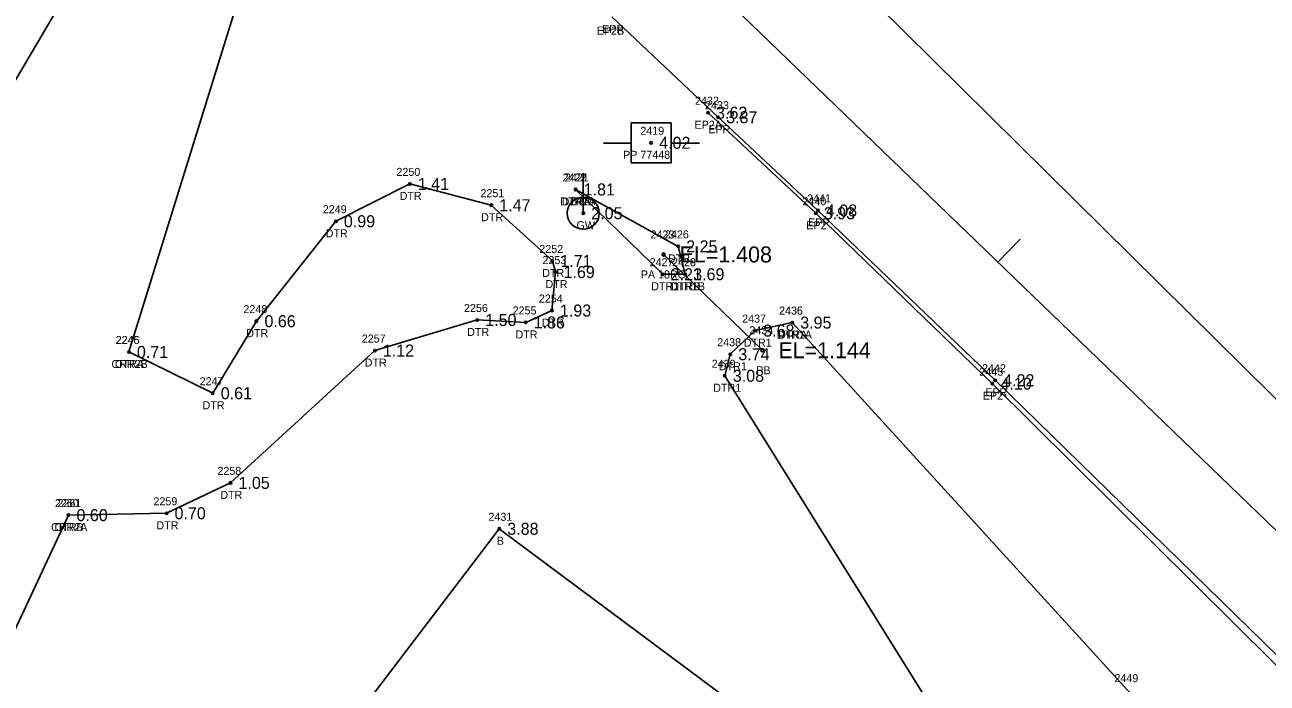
# Model space of a CAD drawing. Extents: x 2608598 to 2610682, y 641451 to 643526.
# Drawn here: x 2609905.8 to 2610061, y 642151 to 642233.2 of the extents above; entities that cross this region are included whole.
import ezdxf

# ---------------------------------------------------------------- set-up
doc = ezdxf.new("R2010")
doc.units = 0
for name, color, linetype in [('RD_EX_Bldg', 7, 'Continuous'), ('RD_EX_Bldg_txCode', 7, 'Continuous'), ('RD_EX_DR_Pipe', 7, 'Continuous'), ('RD_EX_DR_Pipe_txCode', 7, 'Continuous'), ('RD_EX_H2O', 7, 'Continuous'), ('RD_EX_H2O_txCode', 7, 'Continuous'), ('RD_EX_Road', 7, 'Continuous'), ('RD_EX_Road_txCode', 7, 'Continuous'), ('RD_EX_TX_Bldg_ELEV', 7, 'Continuous'), ('RD_EX_TX_H2O_ELEV', 7, 'Continuous'), ('RD_EX_TX_Road_ELEV', 7, 'Continuous'), ('RD_EX_TX_UT_ELEV', 7, 'Continuous'), ('RD_EX_UT', 7, 'Continuous'), ('RD_EX_UT_txCode', 7, 'Continuous'), ('RD_HC_Cl', 7, 'Continuous'), ('RD_HC_Data_Tic', 7, 'Continuous'), ('RD_HC_Survey_ELEV', 7, 'Continuous'), ('RD_SMD_Locator', 7, 'Continuous'), ('RD_TX_Pipe_ElevEX', 7, 'Continuous')]:
    doc.layers.add(name, color=color, linetype=linetype)

msp = doc.modelspace()

# ---------------------------------------------------------------- linework, layer by layer
at = {"layer": 'RD_EX_Bldg'}
msp.add_lwpolyline([(2609946.85, 642146.35), (2609965.06, 642170.24), (2610017.88, 642130.88), (2610000.02, 642106.61), (2609946.85, 642146.35)], dxfattribs=at)
at = {"layer": 'RD_EX_DR_Pipe'}
msp.add_line((2609985.59, 642204.51), (2609997.93, 642192.55), dxfattribs=at)
at = {"layer": 'RD_EX_H2O'}
for points in [[(2609550.15, 642638.19), (2609560.64, 642608.55), (2609596.58, 642544.67), (2609665.26, 642493.63), (2609726.89, 642435.57), (2609728.97, 642442.01), (2609745.88, 642433.78), (2609753.45, 642414.77), (2609764.24, 642411.87), (2609765.65, 642391.82), (2609764.35, 642384.35), (2609816.5, 642340.65), (2609898.67, 642278.63), (2609932.36, 642236.09), (2609918.8, 642192.33)], [(2609918.8, 642192.33), (2609929.27, 642187.18), (2609934.73, 642196.18), (2609944.65, 642208.66), (2609953.89, 642213.33), (2609964.06, 642210.67), (2609971.69, 642203.7), (2609972.09, 642202.31), (2609971.64, 642197.51), (2609968.36, 642196.02), (2609962.31, 642196.33), (2609949.52, 642192.51), (2609931.49, 642175.98), (2609923.5, 642172.18), (2609911.25, 642171.95)], [(2609974.6, 642212.63), (2609985.47, 642202.04), (2609988.28, 642202.04)], [(2609974.6, 642212.63), (2609987.41, 642205.52), (2609988.28, 642202.04)], [(2610001.65, 642196), (2609997.03, 642195), (2609993.92, 642192.05), (2609993.23, 642189.36), (2610025.09, 642138.24), (2610033.21, 642127.17), (2610029.91, 642117.96), (2610026.91, 642107.17), (2610030.12, 642088.07)], [(2610001.65, 642196), (2610043.53, 642150.08), (2610051.56, 642141.98), (2610057.33, 642129.72), (2610057.88, 642123.71), (2610050.62, 642108.28), (2610045.52, 642100), (2610039.29, 642092.45), (2610036.01, 642087.34), (2610033.47, 642085.84), (2610030.12, 642088.07)], [(2609911.25, 642171.95), (2609899.14, 642146.07), (2609837.93, 642059.5)]]:
    msp.add_lwpolyline(points, dxfattribs=at)
at = {"layer": 'RD_EX_Road'}
for points in [[(2609576.61, 642656.06), (2609590.88, 642642.24), (2609605.19, 642628.78), (2609627.58, 642607.09), (2609646.03, 642589.11), (2609702.18, 642534.04), (2609780.35, 642458.95), (2609858.79, 642382.83), (2609938.32, 642306.42), (2610008.62, 642239.32), (2610086.3, 642162.54), (2610164.18, 642089.49), (2610189.2, 642065.46), (2610214.78, 642040.19), (2610225.86, 642030.16), (2610226.32, 642028.39), (2610235.43, 642019.75), (2610260.23, 641995.63), (2610272.39, 641983.25)], [(2609979.13, 642234.19), (2609992.4, 642221.66), (2610004.86, 642210.01), (2610027, 642188.8), (2610067.64, 642149.14), (2610070.8, 642146.19), (2610073.96, 642143.05), (2610116.51, 642103.01), (2610119.68, 642100.06), (2610135.09, 642085.92), (2610148.33, 642073.03), (2610165.14, 642055.61), (2610179.59, 642041.57), (2610196.49, 642024.71), (2610209.86, 642011.42), (2610228.39, 641994.06), (2610252.93, 641970.08), (2610256.35, 641966.74)], [(2609991.14, 642222.22), (2610004.6, 642209.66), (2610026.66, 642188.37), (2610066.82, 642148.56), (2610069.65, 642145.36), (2610071.05, 642141.53), (2610071.68, 642138.94), (2610071.34, 642133.72), (2610072.62, 642129.27)]]:
    msp.add_lwpolyline(points, dxfattribs=at)
at = {"layer": 'RD_EX_UT'}
for p, q in [((2609986.52, 642220.97), (2609981.52, 642220.97)), ((2609981.52, 642220.97), (2609981.52, 642215.97)), ((2609986.52, 642215.97), (2609986.52, 642220.97)), ((2609978.09, 642218.41), (2609981.56, 642218.41)), ((2609986.45, 642218.41), (2609990.09, 642218.41)), ((2609981.52, 642215.97), (2609986.52, 642215.97)), ((2609975.55, 642209.67), (2609975.55, 642214.67))]:
    msp.add_line(p, q, dxfattribs=at)
msp.add_circle((2609975.55, 642209.67), 2, dxfattribs=at)
at = {"layer": 'RD_HC_Cl'}
for p, q in [((2608814.81, 643373.73), (2610092.39, 642140.79)), ((2609912.02, 642238.9), (2609870.22, 642167.84))]:
    msp.add_line(p, q, dxfattribs=at)
at = {"layer": 'RD_HC_Data_Tic'}
msp.add_line((2610027.34, 642203.56), (2610030.12, 642206.44), dxfattribs=at)
at = {"layer": 'RD_SMD_Locator'}
for centre, radius in [((2609991.14, 642222.22), 0.15), ((2609992.4, 642221.66), 0.15), ((2609984.03, 642218.46), 0.15), ((2609953.89, 642213.33), 0.15), ((2609974.6, 642212.63), 0.15), ((2609974.6, 642212.63), 0.15), ((2609964.06, 642210.67), 0.15), ((2609975.55, 642209.67), 0.15), ((2610004.6, 642209.66), 0.15), ((2610004.86, 642210.01), 0.15), ((2609944.65, 642208.66), 0.15), ((2609985.59, 642204.51), 0.2), ((2609987.41, 642205.52), 0.15), ((2609971.69, 642203.7), 0.15), ((2609972.09, 642202.31), 0.15), ((2609985.47, 642202.04), 0.15), ((2609988.28, 642202.04), 0.15), ((2609988.28, 642202.04), 0.15), ((2609971.64, 642197.51), 0.15), ((2609934.73, 642196.18), 0.15), ((2609962.31, 642196.33), 0.15), ((2609968.36, 642196.02), 0.15), ((2610001.65, 642196), 0.15), ((2610001.65, 642196), 0.15), ((2609997.03, 642195), 0.15), ((2609918.8, 642192.33), 0.15), ((2609918.8, 642192.33), 0.15), ((2609949.52, 642192.51), 0.15), ((2609993.92, 642192.05), 0.15), ((2609997.93, 642192.55), 0.2), ((2609993.23, 642189.36), 0.15), ((2610026.66, 642188.37), 0.15), ((2610027, 642188.8), 0.15), ((2609929.27, 642187.18), 0.15), ((2609931.49, 642175.98), 0.15), ((2609911.25, 642171.95), 0.15), ((2609911.25, 642171.95), 0.15), ((2609923.5, 642172.18), 0.15), ((2609965.06, 642170.24), 0.15)]:
    msp.add_circle(centre, radius, dxfattribs=at)

# ---------------------------------------------------------------- texts
at = {"layer": 'RD_EX_Bldg_txCode'}
for s, p in [('2431', (2609963.71, 642171.24)), ('B', (2609964.75, 642168.24))]:
    msp.add_text(s, height=1, dxfattribs=at).set_placement(p)
at = {"layer": 'RD_EX_DR_Pipe_txCode'}
for s, p in [('2423', (2609983.96, 642206.51)), ('PA 18RC', (2609982.74, 642201.51)), ('2434', (2609996.3, 642194.55)), ('PB', (2609997.16, 642189.55))]:
    msp.add_text(s, height=1, dxfattribs=at).set_placement(p)
at = {"layer": 'RD_EX_H2O_txCode'}
for s, p in [('2250', (2609952.22, 642214.33)), ('2422', (2609972.97, 642213.63)), ('2421', (2609973.26, 642213.63)), ('2251', (2609962.71, 642211.67)), ('DTR', (2609952.62, 642211.33)), ('DTR1A', (2609972.68, 642210.63)), ('DTRA', (2609972.85, 642210.63)), ('2249', (2609943.02, 642209.66)), ('DTR', (2609962.79, 642208.67)), ('DTR', (2609943.38, 642206.66)), ('2426', (2609985.76, 642206.52)), ('2252', (2609970.06, 642204.7)), ('2253', (2609970.46, 642203.31)), ('2427', (2609983.84, 642203.04)), ('DTR', (2609986.14, 642203.52)), ('2428', (2609986.65, 642203.04)), ('2429', (2609986.65, 642203.04)), ('DTR', (2609970.43, 642201.7)), ('DTR', (2609970.83, 642200.31)), ('DTR1', (2609984.04, 642200.04)), ('DTR1B', (2609986.38, 642200.04)), ('DTRB', (2609986.54, 642200.04)), ('2254', (2609970.01, 642198.51)), ('2248', (2609933.1, 642197.18)), ('2256', (2609960.66, 642197.33)), ('2255', (2609966.73, 642197.02)), ('2437', (2609995.4, 642196)), ('2436', (2610000, 642197)), ('2435', (2610000.02, 642197)), ('DTR', (2609961.05, 642194.33)), ('DTR', (2609970.37, 642195.51)), ('2246', (2609917.14, 642193.33)), ('2245', (2609917.17, 642193.33)), ('DTR', (2609933.46, 642194.18)), ('2257', (2609947.89, 642193.51)), ('DTR', (2609967.09, 642194.02)), ('2438', (2609992.29, 642193.05)), ('DTR1', (2609995.6, 642193)), ('DTR1A', (2609999.73, 642194)), ('DTRA', (2609999.89, 642194)), ('CRR2B', (2609916.62, 642190.33)), ('DTRA', (2609917.04, 642190.33)), ('DTR', (2609948.25, 642190.51)), ('2439', (2609991.6, 642190.36)), ('DTR1', (2609992.49, 642190.05)), ('2247', (2609927.64, 642188.18)), ('DTR1', (2609991.79, 642187.36)), ('DTR', (2609928, 642185.18)), ('2258', (2609929.86, 642176.98)), ('2260', (2609909.56, 642172.95)), ('2261', (2609909.88, 642172.95)), ('2259', (2609921.87, 642173.18)), ('DTR', (2609930.22, 642173.98)), ('CRR2A', (2609909.07, 642169.95)), ('DTRB', (2609909.51, 642169.95)), ('DTR', (2609922.23, 642170.18)), ('2449', (2610041.9, 642151.08))]:
    msp.add_text(s, height=1, dxfattribs=at).set_placement(p)
at = {"layer": 'RD_EX_Road_txCode'}
for s, p in [('EP2B', (2609977.24, 642231.98)), ('EPR', (2609977.9, 642232.19)), ('2432', (2609989.51, 642223.22)), ('2433', (2609990.77, 642222.66)), ('EP2A', (2609989.45, 642220.22)), ('EPR', (2609991.17, 642219.66)), ('2440', (2610002.93, 642210.66)), ('2441', (2610003.51, 642211.01)), ('EP2', (2610003.4, 642207.66)), ('EPR', (2610003.63, 642208.01)), ('2442', (2610025.37, 642189.8)), ('2443', (2610025.03, 642189.37)), ('EPR', (2610025.77, 642186.8)), ('EP2', (2610025.46, 642186.37))]:
    msp.add_text(s, height=1, dxfattribs=at).set_placement(p)
at = {"layer": 'RD_EX_TX_Bldg_ELEV'}
msp.add_text('3.88', height=1.5, dxfattribs=at).set_placement((2609966.06, 642169.49))
at = {"layer": 'RD_EX_TX_H2O_ELEV'}
for s, p in [('1.41', (2609954.89, 642212.58)), ('1.81', (2609975.6, 642211.88)), ('1.81', (2609975.6, 642211.88)), ('1.47', (2609965.06, 642209.92)), ('0.99', (2609945.65, 642207.91)), ('2.25', (2609988.41, 642204.77)), ('1.71', (2609972.69, 642202.95)), ('1.69', (2609973.09, 642201.56)), ('2.21', (2609986.47, 642201.29)), ('3.69', (2609989.28, 642201.29)), ('3.69', (2609989.28, 642201.29)), ('0.66', (2609935.73, 642195.43)), ('1.50', (2609963.31, 642195.58)), ('1.93', (2609972.64, 642196.76)), ('1.86', (2609969.36, 642195.27)), ('3.68', (2609998.03, 642194.25)), ('3.95', (2610002.65, 642195.25)), ('3.95', (2610002.65, 642195.25)), ('0.71', (2609919.8, 642191.58)), ('0.71', (2609919.8, 642191.58)), ('1.12', (2609950.52, 642191.76)), ('3.74', (2609994.92, 642191.3)), ('3.08', (2609994.23, 642188.61)), ('0.61', (2609930.27, 642186.43)), ('1.05', (2609932.49, 642175.23)), ('0.60', (2609912.25, 642171.2)), ('0.60', (2609912.25, 642171.2)), ('0.70', (2609924.5, 642171.43))]:
    msp.add_text(s, height=1.5, dxfattribs=at).set_placement(p)
at = {"layer": 'RD_EX_TX_Road_ELEV'}
for s, p in [('3.62', (2609992.14, 642221.47)), ('3.87', (2609993.4, 642220.91)), ('3.93', (2610005.6, 642208.91)), ('4.08', (2610005.86, 642209.26)), ('4.10', (2610027.66, 642187.62)), ('4.22', (2610028, 642188.05))]:
    msp.add_text(s, height=1.5, dxfattribs=at).set_placement(p)
at = {"layer": 'RD_EX_TX_UT_ELEV'}
msp.add_text('2.05', height=1.5, dxfattribs=at).set_placement((2609976.55, 642208.92))
at = {"layer": 'RD_EX_UT_txCode'}
for s, p in [('2419', (2609982.68, 642219.46)), ('PP 77448', (2609980.53, 642216.46)), ('2420', (2609973.88, 642210.67)), ('GW', (2609974.71, 642207.67))]:
    msp.add_text(s, height=1, dxfattribs=at).set_placement(p)
at = {"layer": 'RD_HC_Survey_ELEV'}
msp.add_text('4.02', height=1.5, dxfattribs=at).set_placement((2609985.03, 642217.71))
at = {"layer": 'RD_TX_Pipe_ElevEX'}
for s, p in [('EL=1.408', (2609987.59, 642203.51)), ('EL=1.144', (2609999.93, 642191.55))]:
    msp.add_text(s, height=2, dxfattribs=at).set_placement(p)

doc.saveas('drawing.dxf')
